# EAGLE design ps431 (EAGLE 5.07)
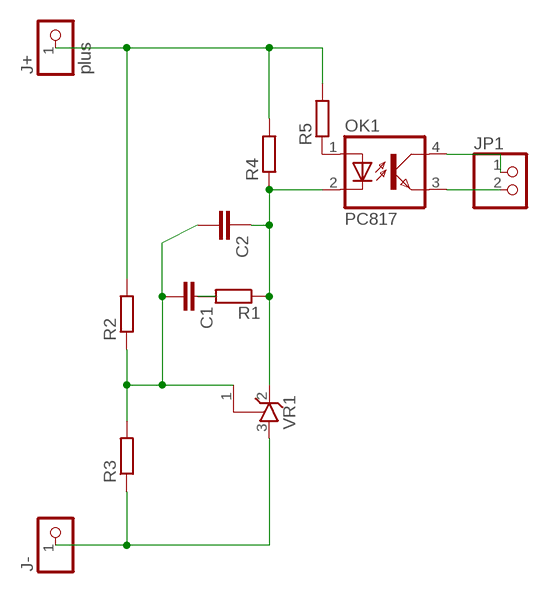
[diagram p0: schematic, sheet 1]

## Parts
C1  C-EUC1206  [C1206]
C2  C-EUC0805  [C0805]
J+  plus  PINHD-1X11X0.4  [1X01]
J-  PINHD-1X11X0.4  [1X01]
JP1  PINHD-1X2STR  [1X02]
OK1  PC817  [DIL04]
R1  R-EU_R0805  [R0805]
R2  R-EU_R0805  [R0805]
R3  R-EU_R0805  [R0805]
R4  R-EU_R0805  [R0805]
R5  R-EU_R0805  [R0805]
VR1  TL431CLPSOT23  [SOT23]

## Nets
N$1: J-.1 R3.1 VR1.3(A)
N$2: C1.2 C2.2 R2.1 R3.2 VR1.1(R)
N$3: C1.1 R1.2
N$4: JP1.2 OK1.3(EMIT)
N$5: J+.1 R2.2 R4.2 R5.2
N$6: C2.1 OK1.2(C) R1.1 R4.1 VR1.2(C)
N$7: OK1.1(A) R5.1
N$8: JP1.1 OK1.4(COL)

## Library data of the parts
C1 C2 = rcl:C-EU: CAPACITOR, European symbol
J+ J- = pinhead:PINHD-1X1: PIN HEADER
JP1 = pinhead:PINHD-1X2: PIN HEADER
OK1 = optocoupler:PC817: SHARP OPTO COUPLER
R1-R5 = rcl:R-EU_: RESISTOR, European symbol
VR1 = v-reg:TL431CLP: VOLTAGE REGULATOR

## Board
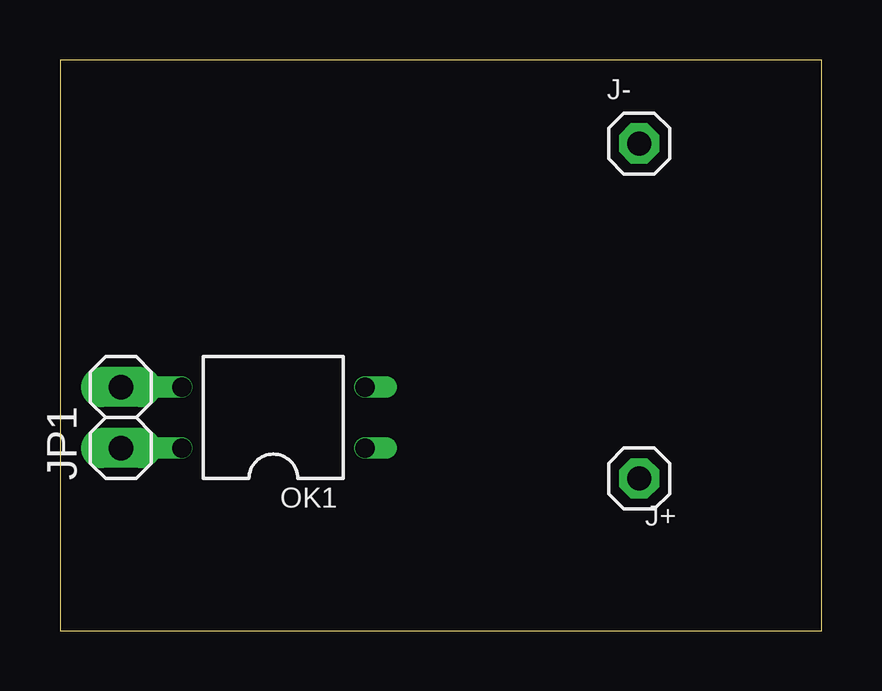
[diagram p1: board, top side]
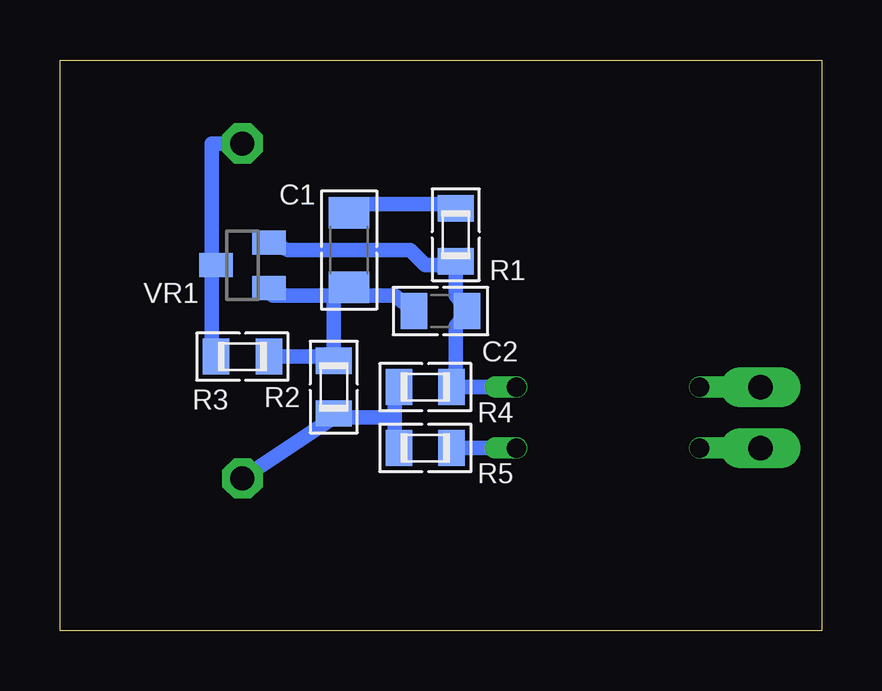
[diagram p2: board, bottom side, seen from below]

Size 31.73 x 23.8 mm. Coordinates in mm from the lower left corner, seen from the top.
Outline: 0,0 31.73,0 31.73,23.8 0,23.8 0,0
Copper layers (1*16): Top 0.035mm / dielectric 1.5mm / Bottom 0.035mm
Design rules "default": minimum track width 10mil, minimum drill 20mil, track to track 8mil, track to pad 8mil, pad to pad 8mil, via to via 8mil, smd to smd 8mil, copper to edge 40mil, drill to drill 8mil, minimum pad ring 1mil, minimum via ring 8mil, stop-mask expansion 4mil, vias tented up to drill 0mil, thermal gap 10mil

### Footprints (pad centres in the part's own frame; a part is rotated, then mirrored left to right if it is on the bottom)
C1206 = smd 1.3 x 1.7: 1 -1.55,0; 2 1.55,0
C0805 = smd 1.1 x 1.5: 1 -1.1,0; 2 1.1,0
1X01 = drill 1 pad 1.676 octagon: 1 0,0
1X02 = drill 1.016 pad 1.676 long: 1 -1.27,0; 2 1.27,0
DIL04 = drill 0.813 offset: 1 -1.27,-3.81; 2 1.27,-3.81; 3 1.27,3.81; 4 -1.27,3.81
R0805 = smd 1.1 x 1.5: 1 -1.1,0; 2 1.1,0
SOT23 = smd 1 x 1.4: 1 -0.95,-1.1; 2 0.95,-1.1; 3 0,1.1

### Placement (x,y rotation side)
C1  19.68,15.88 270 bottom
C2  15.88,13.34 180 bottom
J+  24.13,6.35 0 top
J-  24.13,20.32 0 top
JP1  2.54,8.89 90 top
OK1  8.89,8.89 90 top
R1  15.24,16.51 90 bottom
R2  20.32,10.16 270 bottom
R3  24.13,11.43 0 bottom
R4  16.51,10.16 180 bottom
R5  16.51,7.62 180 bottom
VR1  24.13,15.24 90 bottom

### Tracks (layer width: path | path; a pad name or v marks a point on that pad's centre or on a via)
N$1
  Bottom 0.61: 25.4,15.24 25.4,11.43 R3.1 | 25.4,15.24 25.4,20.32 J-.1 | 25.4,15.24 VR1.3
N$2
  Bottom 0.61: 20.32,13.97 22.86,13.97 VR1.1 | C2.2 17.78,13.97 19.05,13.97 C1.2 20.32,13.97 | 20.32,13.97 20.32,11.43 | 20.32,11.43 R3.2 | 20.32,11.43 R2.1
N$3
  Bottom 0.61: R1.2 15.24,17.78 19.05,17.78 C1.1
N$4
  Bottom 0.61: JP1.2 OK1.3
N$5
  Bottom 0.61: 17.78,8.89 17.78,10.16 R4.2 | 17.78,8.89 17.78,7.62 R5.2 | 17.78,8.89 20.32,8.89 | 20.32,8.89 J+.1 | 20.32,8.89 R2.2
N$6
  Bottom 0.61: OK1.2 15.24,10.16 | 15.24,15.24 16.51,15.24 17.14,15.88 22.23,15.88 VR1.2 | 15.24,15.24 15.24,13.97 C2.1 15.24,12.7 15.24,10.16 | 15.24,15.24 R1.1 | 15.24,10.16 R4.1
N$7
  Bottom 0.61: OK1.1 R5.1
N$8
  Bottom 0.61: JP1.1 OK1.4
